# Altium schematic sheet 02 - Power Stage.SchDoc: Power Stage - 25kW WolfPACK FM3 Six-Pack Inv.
size 431 x 279 mm; Date: 09/2024; DocumentNumber: CRD25DA12N-FMC; Revision: 2.0; SheetNumber: 2; SheetTotal: 9; SheetSize: B
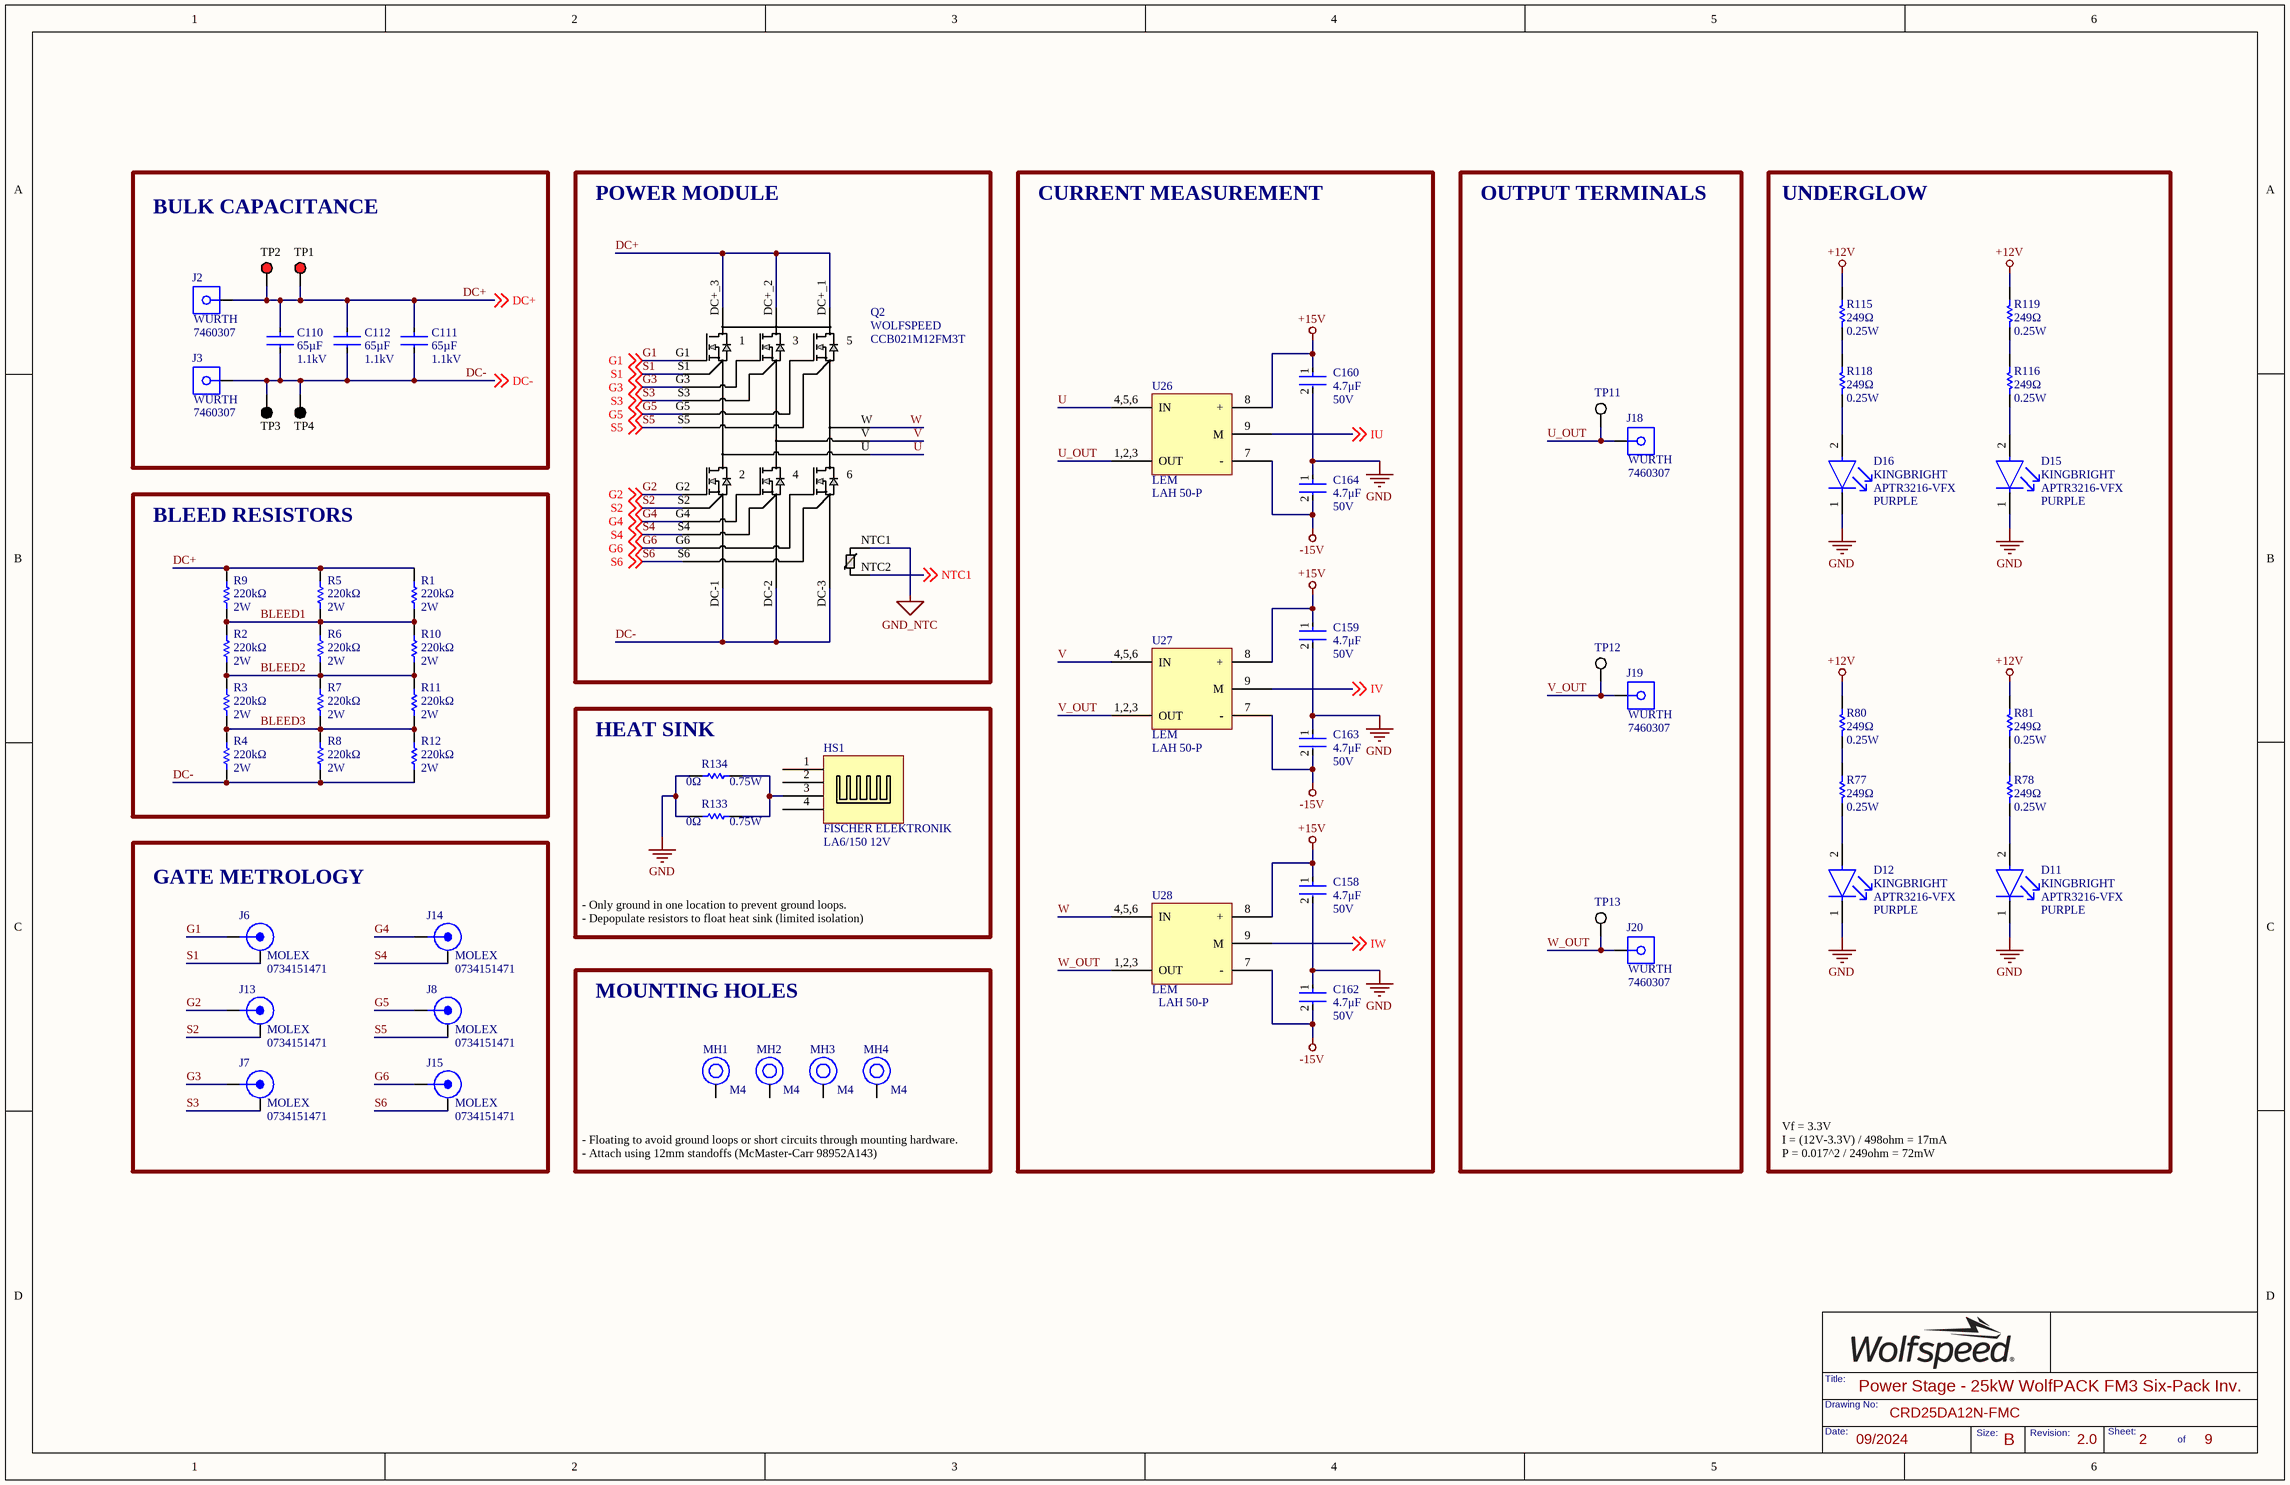
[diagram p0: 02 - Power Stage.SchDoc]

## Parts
C110  Voltage: 1.1kV  Capacitance: 65µF  [C4AQQEW5650A3BJ]  (hidden comment: C4AQQEW5650A3BJ)
C111  Voltage: 1.1kV  Capacitance: 65µF  [C4AQQEW5650A3BJ]  (hidden comment: C4AQQEW5650A3BJ)
C112  Voltage: 1.1kV  Capacitance: 65µF  [C4AQQEW5650A3BJ]  (hidden comment: C4AQQEW5650A3BJ)
C158  Voltage Rating: 50V  Capacitance: 4.7μF  [FP-CL31-IPC_C]  (hidden comment: CL31B475KBHNFNE)
C159  Voltage Rating: 50V  Capacitance: 4.7μF  [FP-CL31-IPC_C]  (hidden comment: CL31B475KBHNFNE)
C160  Voltage Rating: 50V  Capacitance: 4.7μF  [FP-CL31-IPC_C]  (hidden comment: CL31B475KBHNFNE)
C162  Voltage Rating: 50V  Capacitance: 4.7μF  [FP-CL31-IPC_C]  (hidden comment: CL31B475KBHNFNE)
C163  Voltage Rating: 50V  Capacitance: 4.7μF  [FP-CL31-IPC_C]  (hidden comment: CL31B475KBHNFNE)
C164  Voltage Rating: 50V  Capacitance: 4.7μF  [FP-CL31-IPC_C]  (hidden comment: CL31B475KBHNFNE)
D11  Manufacturer Print: KINGBRIGHT  Color: PURPLE  [FP-APTR3216SECK-MFG]  (hidden comment: APTR3216-VFX)
D12  Manufacturer: KINGBRIGHT  Color: PURPLE  [FP-APTR3216SECK-MFG]  (hidden comment: APTR3216-VFX)
D15  Manufacturer Print: KINGBRIGHT  Color: PURPLE  [FP-APTR3216SECK-MFG]  (hidden comment: APTR3216-VFX)
D16  Manufacturer: KINGBRIGHT  Color: PURPLE  [FP-APTR3216SECK-MFG]  (hidden comment: APTR3216-VFX)
HS1  LA6/150 12V  Manufacturer: FISCHER ELEKTRONIK  [LA 6 150 12]
J2  Manufacturer Print: WURTH  [7460307]  (hidden comment: 7460307)
J3  Manufacturer Print: WURTH  [7460307]  (hidden comment: 7460307)
J6  0734151471  Manufacturer Print: MOLEX  [FP-73415-1471-MFG]
J7  0734151471  Manufacturer Print: MOLEX  [FP-73415-1471-MFG]
J8  0734151471  Manufacturer Print: MOLEX  [FP-73415-1471-MFG]
J13  0734151471  Manufacturer Print: MOLEX  [FP-73415-1471-MFG]
J14  0734151471  Manufacturer Print: MOLEX  [FP-73415-1471-MFG]
J15  0734151471  Manufacturer Print: MOLEX  [FP-73415-1471-MFG]
J18  Manufacturer Print: WURTH  [7460307]  (hidden comment: 7460307)
J19  Manufacturer Print: WURTH  [7460307]  (hidden comment: 7460307)
J20  Manufacturer Print: WURTH  [7460307]  (hidden comment: 7460307)
MH1  Size: M4  [MH_M4_P]  (hidden comment: MH_M4_P)
MH2  Size: M4  [MH_M4_P]  (hidden comment: MH_M4_P)
MH3  Size: M4  [MH_M4_P]  (hidden comment: MH_M4_P)
MH4  Size: M4  [MH_M4_P]  (hidden comment: MH_M4_P)
Q2  CCB021M12FM3T  Manufacturer Print: WOLFSPEED  [FM3_SIX-PACK_3PHASE_CRW]
R1  Power Rating: 2W  Resistance: 220kΩ  [FP-CRGP2512-IPC_C]  (hidden comment: CRGP2512F220K)
R2  Power Rating: 2W  Resistance: 220kΩ  [FP-CRGP2512-IPC_C]  (hidden comment: CRGP2512F220K)
R3  Power Rating: 2W  Resistance: 220kΩ  [FP-CRGP2512-IPC_C]  (hidden comment: CRGP2512F220K)
R4  Power Rating: 2W  Resistance: 220kΩ  [FP-CRGP2512-IPC_C]  (hidden comment: CRGP2512F220K)
R5  Power Rating: 2W  Resistance: 220kΩ  [FP-CRGP2512-IPC_C]  (hidden comment: CRGP2512F220K)
R6  Power Rating: 2W  Resistance: 220kΩ  [FP-CRGP2512-IPC_C]  (hidden comment: CRGP2512F220K)
R7  Power Rating: 2W  Resistance: 220kΩ  [FP-CRGP2512-IPC_C]  (hidden comment: CRGP2512F220K)
R8  Power Rating: 2W  Resistance: 220kΩ  [FP-CRGP2512-IPC_C]  (hidden comment: CRGP2512F220K)
R9  Power Rating: 2W  Resistance: 220kΩ  [FP-CRGP2512-IPC_C]  (hidden comment: CRGP2512F220K)
R10  Power Rating: 2W  Resistance: 220kΩ  [FP-CRGP2512-IPC_C]  (hidden comment: CRGP2512F220K)
R11  Power Rating: 2W  Resistance: 220kΩ  [FP-CRGP2512-IPC_C]  (hidden comment: CRGP2512F220K)
R12  Power Rating: 2W  Resistance: 220kΩ  [FP-CRGP2512-IPC_C]  (hidden comment: CRGP2512F220K)
R77  Resistance: 249Ω  Power Rating: 0.25W  [FP-MCR18-IPC_A]  (hidden comment: RC1206FR-07249RL)
R78  Resistance: 249Ω  Power Rating: 0.25W  [FP-MCR18-IPC_A]  (hidden comment: RC1206FR-07249RL)
R80  Resistance: 249Ω  Power Rating: 0.25W  [FP-MCR18-IPC_A]  (hidden comment: RC1206FR-07249RL)
R81  Resistance: 249Ω  Power Rating: 0.25W  [FP-MCR18-IPC_A]  (hidden comment: RC1206FR-07249RL)
R115  Resistance: 249Ω  Power Rating: 0.25W  [FP-MCR18-IPC_A]  (hidden comment: RC1206FR-07249RL)
R116  Resistance: 249Ω  Power Rating: 0.25W  [FP-MCR18-IPC_A]  (hidden comment: RC1206FR-07249RL)
R118  Resistance: 249Ω  Power Rating: 0.25W  [FP-MCR18-IPC_A]  (hidden comment: RC1206FR-07249RL)
R119  Resistance: 249Ω  Power Rating: 0.25W  [FP-MCR18-IPC_A]  (hidden comment: RC1206FR-07249RL)
R133  value 0Ω  Power Rating: 0.75W  [RESC3125X70X40NL20T20]  (hidden comment: CRCW12100000Z0EAHP)
R134  value 0Ω  Power Rating: 0.75W  [RESC3125X70X40NL20T20]  (hidden comment: CRCW12100000Z0EAHP)
TP1  5010  [KSTN-5010_V]  (value not drawn)
TP2  5010  [KSTN-5010_V]  (value not drawn)
TP3  5011  [KSTN-5011_V]  (value not drawn)
TP4  5011  [KSTN-5011_V]  (value not drawn)
TP11  5012  [KSTN-5012_V]  (value not drawn)
TP12  5012  [KSTN-5012_V]  (value not drawn)
TP13  5012  [KSTN-5012_V]  (value not drawn)
U26  LAH 50-P  Manufacturer Print: LEM  [LAH 50-P]
U27  LAH 50-P  Manufacturer Print: LEM  [LAH 50-P]
U28  LAH 50-P  Manufacturer Print: LEM  [LAH 50-P]

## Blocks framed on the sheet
BULK CAPACITANCE: C110-C112 J2 J3 TP1-TP4
POWER MODULE: Q2
CURRENT MEASUREMENT: C158-C160 C162-C164 U26-U28
OUTPUT TERMINALS: J18-J20 TP11-TP13
UNDERGLOW: D11 D12 D15 D16 R77 R78 R80 R81 R115 R116 R118 R119
BLEED RESISTORS: R1-R12
HEAT SINK: HS1 R133 R134
GATE METROLOGY: J6-J8 J13-J15
MOUNTING HOLES: MH1-MH4

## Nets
+12V: R80.1 R81.1 R115.1 R119.1
+15V: C158.1 C159.1 C160.1 U26.8(+) U27.8(+) U28.8(+)
-15V: C162.2 C163.2 C164.2 U26.7(-) U27.7(-) U28.7(-)
GND: C158.2 C159.2 C160.2 C162.1 C163.1 C164.1 D11.1(C) D12.1(C) D15.1(C) D16.1(C) R133.1 R134.1
GND_NTC: Q2.NTC1
BLEED1: R1.1 R2.2 R5.1 R6.2 R9.1 R10.2
BLEED2: R2.1 R3.2 R6.1 R7.2 R10.1 R11.2
BLEED3: R3.1 R4.2 R7.1 R8.2 R11.1 R12.2
DC+: C110.1,2(+) C111.1,2(+) C112.1,2(+) J2.1,2,3,4,5,6,7,8 Q2.DC+_1 Q2.DC+_2 Q2.DC+_3 R1.2 R5.2 R9.2 TP1.1 TP2.1 ; off-sheet DC+
DC-: C110.3,4 C111.3,4 C112.3,4 J3.1,2,3,4,5,6,7,8 Q2.DC-1 Q2.DC-2 Q2.DC-3 R4.1 R8.1 R12.1 TP3.1 TP4.1 ; off-sheet DC-
G1: J6.1(CENTER) Q2.G1 ; off-sheet G1
G2: J13.1(CENTER) Q2.G2 ; off-sheet G2
G3: J7.1(CENTER) Q2.G3 ; off-sheet G3
G4: J14.1(CENTER) Q2.G4 ; off-sheet G4
G5: J8.1(CENTER) Q2.G5 ; off-sheet G5
G6: J15.1(CENTER) Q2.G6 ; off-sheet G6
IU: U26.9(M) ; off-sheet IU
IV: U27.9(M) ; off-sheet IV
IW: U28.9(M) ; off-sheet IW
NTC1: Q2.NTC2 ; off-sheet NTC1
S1: J6.2,3,4,5(SHIELD) Q2.S1 ; off-sheet S1
S2: J13.2,3,4,5(SHIELD) Q2.S2 ; off-sheet S2
S3: J7.2,3,4,5(SHIELD) Q2.S3 ; off-sheet S3
S4: J14.2,3,4,5(SHIELD) Q2.S4 ; off-sheet S4
S5: J8.2,3,4,5(SHIELD) Q2.S5 ; off-sheet S5
S6: J15.2,3,4,5(SHIELD) Q2.S6 ; off-sheet S6
U: Q2.U U26.4,5,6(IN)
U_OUT: J18.1,2,3,4,5,6,7,8 TP11.1 U26.1,2,3(OUT)
V: Q2.V U27.4,5,6(IN)
V_OUT: J19.1,2,3,4,5,6,7,8 TP12.1 U27.1,2,3(OUT)
W: Q2.W U28.4,5,6(IN)
W_OUT: J20.1,2,3,4,5,6,7,8 TP13.1 U28.1,2,3(OUT)
NetD11_2: D11.2(A) R78.2
NetD12_2: D12.2(A) R77.2
NetD15_2: D15.2(A) R116.2
NetD16_2: D16.2(A) R118.2
NetHS1_3: HS1.3 R133.2 R134.2
NetR77_1: R77.1 R80.2
NetR78_1: R78.1 R81.2
NetR115_2: R115.2 R118.1
NetR116_1: R116.1 R119.2

Not connected (* = marked no-connect by the designer): HS1 1 2 4; MH1 1; MH2 1; MH3 1; MH4 1

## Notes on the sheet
- - Only ground in one location to prevent ground loops.
  - Depopulate resistors to float heat sink (limited isolation)
- - Floating to avoid ground loops or short circuits through mounting hardware.
  - Attach using 12mm standoffs (McMaster-Carr 98952A143)
- Vf = 3.3V
  I = (12V-3.3V) / 498ohm = 17mA
  P = 0.017^2 / 249ohm = 72mW

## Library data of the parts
C110-C112 = C4AQQEW5650A3BJ: CAP FILM 65UF 5% 1.1KVDC RAD; Manufacturer: KEMET; Value: 65µF
C158-C160 C162-C164 = CMP-13271-001123-1: CAP CER 4.7UF 50V X7R 1206; Manufacturer: SAMSUNG; Tolerance: 10%; Value: 4.7μF
D11 D12 D15 D16 = APTR3216-VFX: LED PURPLE CLEAR 1206 SMD
HS1 = LA 6 150 12: HEATSINK EXTRUSION 150MM; Natural Thermal Resistance: 0.175°C/W; Power Consumption: 2.9W
J2 J3 J18-J20 = 7460307: TERM REDCUBE M4 8PIN PCB; Manufacturer: WURTH ELEKTRONIK; Current Rating: 80A; Number of Contacts: 8; Insulation: Non-Insulated
J6-J8 J13-J15 = 0734151471: CONN MMCX JACK STR 50 OHM PCB; Manufacturer Part Number: 73415-1471; Body Material: Brass; Body Plating: Gold; Impedance: 50R; Connector Type: PCB,MMCX,Coaxial; Max Frequency: 6GHz; Gender: Female
MH1-MH4 = MH_M4_P: HEX STANDOFF M4 ALUMINUM 51MM F-F; Manufacturer: MCMASTER-CARR; Manufacturer Part Number: 95947A552
Q2 = CCB021M12FM3: SIC 6N-CH 1200V 30A MODULE; Mfr_Name: Cree Wolfspeed; Type: DEV
R1-R12 = CMP-03211-002966-1: RES 220K OHM 1% 2W 2512; Manufacturer: TE; Value: 220kΩ; Temperature Coefficient: ±100ppm/°C; Tolerance: 0.01; Voltage Rating: 500V
R77 R78 R80 R81 R115 R116 R118 R119 = RC1206FR-07249RL: RES 249 OHM 1% 1/4W 1206; Manufacturer: YAGEO; Voltage Rating: 200V; Temperature Coefficient: 100ppm/°C; Max Power Dissipation: 250mW; Value: 249Ω
R133 R134 = CRCW12100000Z0EAHP: RES SMD 0 OHM JUMPER 3/4W 1210; Manufacturer: VISHAY DALE; Max Power Dissipation: 750mW
TP1 TP2 = CMP-1672-00002-4: PC TEST POINT MULTIPURPOSE RED; Manufacturer: KEYSTONE
TP3 TP4 = CMP-1672-00003-4: PC TEST POINT MULTIPURPOSE BLACK; Manufacturer: KEYSTONE
TP11-TP13 = CMP-1672-00004-4: PC TEST POINT MULTIPURPOSE WHITE; Manufacturer: KEYSTONE
U26-U28 = LAH 50-P: SENSOR CURRENT HALL 50A AC/DC; Frequency: 200kHz; Number of Channels: 1; Response Time: 0.5us; Max Supply Current: 35mA; Polarity: Bidirectional; Linearity: 0.15%; Accuracy: 0.25%; Operating Supply Voltage: 15V; Secondary Current: 25mA; Overall Height: 21mm; Overall Depth: 14.93mm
